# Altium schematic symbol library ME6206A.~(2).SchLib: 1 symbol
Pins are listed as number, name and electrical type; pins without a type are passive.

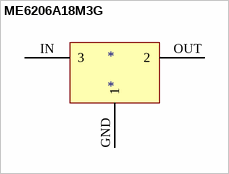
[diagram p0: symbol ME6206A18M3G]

## ME6206A18M3G
designator *
pins: GND 1, IN 3, OUT 2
